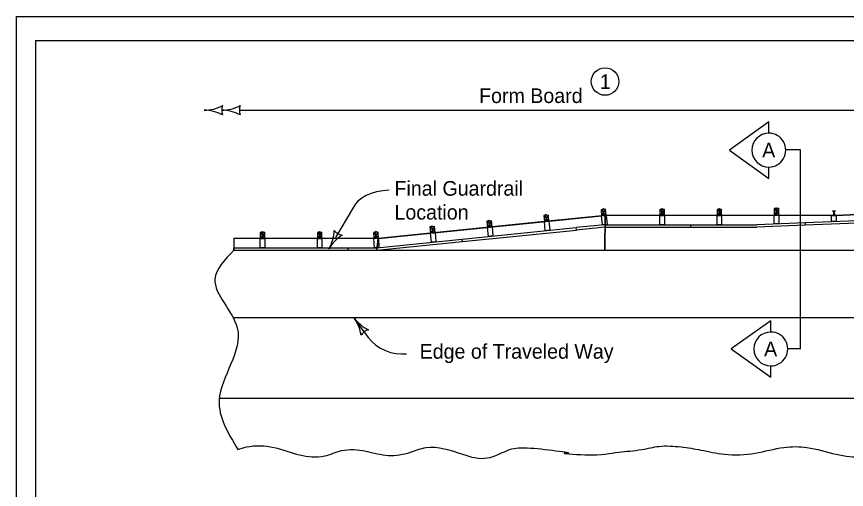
# Model space of a CAD drawing. Extents: x 6410 to 81668, y 3928 to 11667.
# Drawn here: x 10133 to 11038, y 9428 to 9944 of the extents above; entities that cross this region are included whole.
import ezdxf

# ---------------------------------------------------------------- set-up
doc = ezdxf.new("R2010")
doc.units = 0
for name, color, linetype in [('dsnCellElements', 7, 'Continuous'), ('dsnNonPlotable', 7, 'Continuous'), ('dsnShtPlotShapeBatchPrint', 7, 'Continuous'), ('dsnStdBlockModified', 7, 'Continuous'), ('Level 10', 7, 'Continuous'), ('Level 11', 7, 'Continuous'), ('Level 14', 7, 'Continuous'), ('Level 3', 7, 'Continuous'), ('Level 7', 7, 'Continuous'), ('Level 8', 7, 'Continuous')]:
    doc.layers.add(name, color=color, linetype=linetype)

msp = doc.modelspace()

# ---------------------------------------------------------------- linework, layer by layer
at = {"layer": 'dsnCellElements'}
for p, q in [((10499.16, 9734.25), (10480.61, 9702.91)), ((10512.77, 9599.09), (10500.66, 9615.54)), ((10552.86, 9576.02), (10558.31, 9576.02))]:
    msp.add_line(p, q, dxfattribs=at)
for centre, radius, start, end in [((10436.84, 9712.41), 42.5, 329.37973, 357.45222), ((10491.57, 9721.43), 16.42, 221.64638, 257.11308), ((10509.99, 9669.12), 42.5, 121.30724, 149.37973), ((10534.88, 9640.74), 42.5, 216.37256, 244.44505), ((10466.44, 9590.33), 42.5, 8.30007, 36.37256), ((10521.79, 9586.84), 16.42, 108.63921, 144.10591), ((10552.92, 9622.48), 46.46, 210.22743, 270)]:
    msp.add_arc(centre, radius, start, end, dxfattribs=at)
msp.add_ellipse((10580.25, 9695.21), major_axis=(-81.09, 39.04), ratio=0.555556, start_param=5.482641, end_param=6.283185, dxfattribs=at)
at = {"layer": 'dsnNonPlotable'}
for q in [(10153.18, 8307.9), (13248.87, 9917.9)]:
    msp.add_line((10153.18, 9917.9), q, dxfattribs=at)
at = {"layer": 'dsnShtPlotShapeBatchPrint'}
for p, q in [((10376.45, 9842.03), (11398.86, 9842.03)), ((11501.75, 9746.48), (11026.46, 9726.96)), ((10708.69, 9720.37), (10527.39, 9701.88)), ((10775.18, 9726.96), (10708.69, 9720.38)), ((10708.69, 9720.38), (10708.69, 9720.37)), ((10775.18, 9726.96), (10774.8, 9689.17)), ((10774.8, 9689.17), (10775.18, 9726.96)), ((11026.46, 9726.96), (10775.18, 9726.96)), ((10775.18, 9726.96), (10775.18, 9726.96)), ((10369.67, 9701.88), (10369.64, 9689.17)), ((10527.39, 9701.87), (10369.67, 9701.88)), ((10527.39, 9701.87), (10525.89, 9689.17)), ((10525.89, 9689.17), (10527.39, 9701.87)), ((10527.39, 9701.88), (10527.39, 9701.87)), ((10527.39, 9701.87), (10527.39, 9701.87)), ((10369.64, 9689.17), (10525.89, 9689.17)), ((10525.89, 9689.17), (10774.8, 9689.17)), ((10774.8, 9689.17), (11806.49, 9689.17))]:
    msp.add_line(p, q, dxfattribs=at)
for centre, radius, start, end in [((10337.23, 9884.37), 42.5, 270, 298.07249), ((10356.45, 9884.37), 42.5, 270, 298.07249), ((10372.87, 9841.87), 16.42, 162.26665, 197.73335), ((10392.09, 9841.87), 16.42, 162.26665, 197.73335), ((10337.23, 9799.37), 42.5, 61.92751, 90), ((10356.45, 9799.37), 42.5, 61.92751, 90)]:
    msp.add_arc(centre, radius, start, end, dxfattribs=at)
at = {"layer": 'dsnStdBlockModified'}
for p, q in [((11026.36, 9726.96), (11501.75, 9746.48)), ((11404.96, 9735.52), (10993.39, 9719.06)), ((11405.06, 9732.82), (10993.39, 9716.35)), ((11023.02, 9731.85), (11023.02, 9731.7)), ((11026.36, 9731.85), (11023.02, 9731.85)), ((11023.02, 9731.7), (11024.19, 9731.7)), ((11024.61, 9731.28), (11024.61, 9727.53)), ((11024.77, 9727.53), (11024.77, 9731.28)), ((11025.18, 9731.7), (11026.36, 9731.7)), ((11025.78, 9729.15), (11025.26, 9729.15)), ((11025.26, 9729.15), (11025.26, 9727.63)), ((11025.78, 9727.63), (11025.78, 9729.15)), ((11026.36, 9731.7), (11026.36, 9731.85)), ((10527.39, 9701.88), (10775.18, 9726.96)), ((11023.02, 9726.96), (10775.18, 9726.96)), ((11022.08, 9720.31), (11022.08, 9727.27)), ((11022.08, 9727.27), (11022.71, 9727.27)), ((11027.08, 9720.31), (11022.08, 9720.31)), ((11022.71, 9726.96), (11022.71, 9727.27)), ((11026.46, 9726.96), (11022.71, 9726.96)), ((11023.02, 9727.11), (11023.02, 9726.96)), ((11024.19, 9727.11), (11023.02, 9727.11)), ((11023.02, 9726.96), (11026.36, 9726.96)), ((11025, 9727.63), (11024.92, 9727.58)), ((11024.92, 9727.21), (11024.92, 9727.58)), ((11025, 9727.63), (11025.97, 9727.63)), ((11026.36, 9727.11), (11025.18, 9727.11)), ((11025.22, 9727.17), (11025.22, 9727.58)), ((11025.82, 9727.17), (11025.82, 9727.58)), ((11025.97, 9727.63), (11026.04, 9727.63)), ((11026.12, 9727.58), (11026.04, 9727.63)), ((11026.04, 9727.11), (11026.12, 9727.17)), ((11026.12, 9727.17), (11026.12, 9727.58)), ((11026.36, 9726.96), (11026.36, 9727.11)), ((11026.46, 9727.27), (11027.08, 9727.27)), ((11026.46, 9727.27), (11026.46, 9726.96)), ((11027.08, 9727.27), (11027.08, 9720.31)), ((10993.39, 9719.06), (10940.63, 9716.95)), ((10993.5, 9716.36), (10940.65, 9714.24)), ((10993.39, 9719.06), (10993.5, 9716.36)), ((10993.39, 9719.06), (10993.5, 9716.36)), ((10369.67, 9701.88), (10369.64, 9691.87)), ((10527.39, 9701.88), (10369.67, 9701.88)), ((10369.64, 9689.17), (11983.35, 9689.17)), ((10369.86, 9615.54), (11983.65, 9615.54))]:
    msp.add_line(p, q, dxfattribs=at)
for centre, start, end in [((11024.19, 9731.28), 359.99336, 90.00253), ((11025.18, 9731.28), 90.00734, 179.99635), ((11024.19, 9727.53), 270.00734, 359.99635), ((11025.18, 9727.53), 264.71743, 270.00253)]:
    msp.add_arc(centre, 0.417, start, end, dxfattribs=at)
for points in [[(11025.22, 9727.58), (11025.2, 9727.6), (11025.15, 9727.63), (11025.06, 9727.64), (11024.99, 9727.62), (11024.94, 9727.6), (11024.92, 9727.58)], [(11025.12, 9727.12), (11025.13, 9727.13), (11025.17, 9727.13), (11025.2, 9727.15), (11025.22, 9727.17)], [(11025.82, 9727.58), (11025.77, 9727.6), (11025.66, 9727.63), (11025.51, 9727.64), (11025.36, 9727.62), (11025.27, 9727.6), (11025.22, 9727.58)], [(11025.22, 9727.17), (11025.27, 9727.15), (11025.38, 9727.12), (11025.54, 9727.11), (11025.69, 9727.13), (11025.78, 9727.15), (11025.82, 9727.17)], [(11026.12, 9727.58), (11026.11, 9727.59), (11026.07, 9727.61), (11026.01, 9727.63), (11025.94, 9727.64), (11025.87, 9727.61), (11025.84, 9727.59), (11025.82, 9727.58)], [(11025.82, 9727.17), (11025.84, 9727.16), (11025.87, 9727.14), (11025.94, 9727.11), (11026.01, 9727.12), (11026.07, 9727.14), (11026.11, 9727.16), (11026.12, 9727.17)]]:
    msp.add_open_spline(points, degree=3, dxfattribs=at)
for points in [[(10369.64, 9689.17), (10348.99, 9657.61), (10373.36, 9604.53), (10353.66, 9525.43), (10373.93, 9471.82)], [(10373.93, 9471.82), (10383.36, 9474.4), (10413.58, 9473.83), (10441.52, 9465.84), (10468.89, 9464.7), (10487.14, 9470.4), (10513.94, 9469.83), (10538.46, 9465.27), (10562.41, 9468.69), (10579.52, 9473.83), (10619.43, 9466.41), (10646.23, 9462.42), (10670.75, 9471.54), (10693.56, 9473.26), (10732.34, 9467.55), (10731.77, 9467.55), (10752.92, 9465.95), (10789.99, 9468.8), (10815.08, 9471.65), (10833.9, 9475.08), (10857.85, 9474.5), (10879.51, 9471.08), (10905.17, 9466.52), (10938.82, 9467.66), (10970.18, 9473.93), (10995.27, 9473.93), (11027.2, 9466.52), (11056.29, 9463.67), (11089.93, 9470.51), (11122.43, 9473.93), (11156.65, 9467.09), (11182.31, 9464.24), (11204.54, 9467.66), (11232.49, 9483.06), (11242.75, 9485.34), (11267.27, 9487.63), (11297.93, 9488.2), (11319.03, 9488.2), (11372.34, 9478.91)]]:
    msp.add_spline(points, degree=3, dxfattribs=at)
at = {"layer": 'Level 10'}
for p, q in [((10988.26, 9798.63), (10972.49, 9798.63)), ((10988.26, 9581.35), (10988.26, 9798.63)), ((10988.26, 9581.35), (10974.31, 9581.35))]:
    msp.add_line(p, q, dxfattribs=at)
for points in [[(10953.7, 9816.82), (10953.7, 9829.14), (10910.57, 9798.33), (10953.7, 9767.52), (10953.7, 9779.84)], [(10955.82, 9599.83), (10955.82, 9612.16), (10912.69, 9581.35), (10955.82, 9550.54), (10955.82, 9562.86)]]:
    msp.add_lwpolyline(points, dxfattribs=at)
for centre, start, end in [((10953.7, 9798.33), 90.00083, 269.99917), ((10953.7, 9798.33), 269.99917, 90.00083), ((10955.82, 9581.35), 90.00083, 269.99917), ((10955.82, 9581.35), 269.99917, 90.00083)]:
    msp.add_arc(centre, 18.49, start, end, dxfattribs=at)
at = {"layer": 'Level 11'}
msp.add_line((10353.26, 9527.62), (11995.29, 9527.62), dxfattribs=at)
at = {"layer": 'Level 14'}
for p, q in [((10770.49, 9733.29), (10776.13, 9727.16)), ((10775.47, 9733.79), (10771.15, 9726.66)), ((10772.88, 9734.51), (10772.88, 9734.58)), ((10773.64, 9726.91), (10772.98, 9733.54)), ((10834.64, 9733.62), (10839.64, 9726.96)), ((10839.64, 9733.62), (10834.64, 9726.96)), ((10837.14, 9734.6), (10837.14, 9734.67)), ((10837.14, 9726.96), (10837.14, 9733.62)), ((10897.14, 9733.62), (10902.14, 9726.96)), ((10902.14, 9733.62), (10897.14, 9726.96)), ((10899.64, 9734.6), (10899.64, 9734.67)), ((10899.64, 9726.96), (10899.64, 9733.62)), ((10959.64, 9734.49), (10964.64, 9727.82)), ((10964.64, 9734.49), (10959.64, 9727.82)), ((10962.14, 9735.46), (10962.14, 9735.53)), ((10962.14, 9727.82), (10962.14, 9734.49)), ((10645.84, 9720.76), (10651.48, 9714.63)), ((10650.82, 9721.26), (10646.51, 9714.13)), ((10648.23, 9721.98), (10648.22, 9722.05)), ((10648.99, 9714.38), (10648.33, 9721.01)), ((10708.03, 9727.01), (10713.67, 9720.88)), ((10713, 9727.51), (10708.69, 9720.38)), ((10708.69, 9720.38), (10713.67, 9720.88)), ((10709.69, 9710.42), (10708.69, 9720.38)), ((10710.42, 9728.23), (10710.41, 9728.3)), ((10711.18, 9720.63), (10710.51, 9727.26)), ((10713.67, 9720.88), (10714.67, 9710.92)), ((10771.15, 9726.66), (10776.13, 9727.16)), ((10773.64, 9726.91), (10771.15, 9726.66)), ((10773.64, 9726.91), (10771.15, 9726.66)), ((10772.15, 9716.7), (10771.15, 9726.66)), ((10776.13, 9727.16), (10777.13, 9717.2)), ((10834.64, 9726.96), (10839.64, 9726.96)), ((10834.64, 9716.95), (10834.64, 9726.96)), ((10839.64, 9726.96), (10839.64, 9716.95)), ((10897.14, 9726.96), (10902.14, 9726.96)), ((10897.14, 9716.95), (10897.14, 9726.96)), ((10902.14, 9726.96), (10902.14, 9716.95)), ((10959.64, 9727.82), (10964.64, 9727.82)), ((10959.64, 9717.81), (10959.64, 9727.82)), ((10964.64, 9727.82), (10964.64, 9717.81)), ((10583.66, 9714.55), (10589.3, 9708.38)), ((10588.64, 9715.05), (10584.33, 9707.88)), ((10586.05, 9715.77), (10586.05, 9715.84)), ((10586.81, 9708.13), (10586.15, 9714.8)), ((10618.9, 9701.3), (10743.28, 9713.8)), ((10619.17, 9698.6), (10743.55, 9711.1)), ((10646.51, 9714.13), (10651.49, 9714.63)), ((10647.51, 9704.17), (10646.51, 9714.13)), ((10651.49, 9714.63), (10652.49, 9704.67)), ((10714.67, 9710.92), (10709.69, 9710.42)), ((10774.64, 9716.95), (10743.28, 9713.8)), ((10743.55, 9711.1), (10743.28, 9713.8)), ((10743.55, 9711.12), (10743.28, 9713.8)), ((10774.64, 9714.24), (10743.55, 9711.12)), ((10777.13, 9717.2), (10772.15, 9716.7)), ((10774.64, 9716.95), (10868.39, 9716.95)), ((10774.64, 9714.24), (10868.39, 9714.24)), ((10839.64, 9716.95), (10834.64, 9716.95)), ((10868.39, 9714.24), (10868.39, 9716.95)), ((10868.39, 9716.95), (10940.63, 9716.95)), ((10868.39, 9714.24), (10868.39, 9716.95)), ((10868.39, 9714.24), (10940.65, 9714.24)), ((10902.14, 9716.95), (10897.14, 9716.95)), ((10964.64, 9717.81), (10959.64, 9717.81)), ((10398.39, 9708.55), (10403.39, 9701.88)), ((10403.39, 9708.55), (10398.39, 9701.88)), ((10398.39, 9701.88), (10403.4, 9701.88)), ((10398.39, 9691.87), (10398.39, 9701.88)), ((10400.89, 9709.52), (10400.89, 9709.59)), ((10400.89, 9701.88), (10400.89, 9708.55)), ((10403.4, 9701.88), (10403.4, 9691.87)), ((10460.89, 9708.55), (10465.89, 9701.88)), ((10465.89, 9708.55), (10460.89, 9701.88)), ((10460.89, 9701.88), (10465.9, 9701.88)), ((10460.89, 9691.87), (10460.89, 9701.88)), ((10463.39, 9709.52), (10463.39, 9709.59)), ((10463.39, 9701.88), (10463.39, 9708.55)), ((10465.9, 9701.88), (10465.9, 9691.87)), ((10522.28, 9708.61), (10527.61, 9702.17)), ((10527.28, 9708.86), (10522.62, 9701.92)), ((10522.62, 9701.92), (10527.61, 9702.17)), ((10523.11, 9691.88), (10522.62, 9701.92)), ((10524.73, 9709.71), (10524.73, 9709.78)), ((10525.11, 9702.05), (10524.78, 9708.74)), ((10527.61, 9702.17), (10528.11, 9692.13)), ((10584.33, 9707.88), (10589.3, 9708.38)), ((10585.32, 9697.87), (10584.33, 9707.88)), ((10589.3, 9708.38), (10590.3, 9698.38)), ((10652.49, 9704.67), (10647.51, 9704.17)), ((10525.62, 9691.87), (10618.9, 9701.3)), ((10525.89, 9689.17), (10619.17, 9698.59)), ((10590.3, 9698.38), (10585.32, 9697.87)), ((10619.17, 9698.59), (10618.9, 9701.3)), ((10619.17, 9698.6), (10618.9, 9701.3)), ((10369.64, 9691.87), (10494.64, 9691.87)), ((10369.64, 9689.17), (10369.64, 9691.87)), ((10369.64, 9689.17), (10494.64, 9689.17)), ((10403.4, 9691.87), (10398.39, 9691.87)), ((10465.9, 9691.87), (10460.89, 9691.87)), ((10494.64, 9691.87), (10525.62, 9691.87)), ((10494.64, 9689.17), (10494.64, 9691.87)), ((10494.64, 9689.17), (10525.89, 9689.17)), ((10528.11, 9692.13), (10523.11, 9691.88))]:
    msp.add_line(p, q, dxfattribs=at)
for points in [[(10771.15, 9726.66), (10776.13, 9727.16), (10775.47, 9733.79), (10770.49, 9733.29)], [(10834.64, 9726.96), (10839.64, 9726.96), (10839.64, 9733.62), (10834.64, 9733.62)], [(10897.14, 9726.96), (10902.14, 9726.96), (10902.14, 9733.62), (10897.14, 9733.62)], [(10959.64, 9727.82), (10964.64, 9727.82), (10964.64, 9734.49), (10959.64, 9734.49)], [(10646.51, 9714.13), (10651.48, 9714.63), (10650.82, 9721.26), (10645.84, 9720.76)], [(10708.69, 9720.38), (10713.67, 9720.88), (10713, 9727.51), (10708.03, 9727.01)], [(10584.33, 9707.88), (10589.3, 9708.38), (10588.64, 9715.05), (10583.66, 9714.55)], [(10398.39, 9701.88), (10403.39, 9701.88), (10403.39, 9708.55), (10398.39, 9708.55)], [(10460.89, 9701.88), (10465.89, 9701.88), (10465.89, 9708.55), (10460.89, 9708.55)], [(10522.62, 9701.92), (10527.61, 9702.17), (10527.28, 9708.86), (10522.28, 9708.61)]]:
    msp.add_lwpolyline(points, close=True, dxfattribs=at)
for points in [[(10772.65, 9733.51), (10772.6, 9733.94), (10773.27, 9734), (10773.31, 9733.57)], [(10772.74, 9733.95), (10772.69, 9734.49), (10773.08, 9734.53), (10773.13, 9733.99)], [(10836.8, 9733.62), (10836.8, 9734.06), (10837.47, 9734.06), (10837.47, 9733.62)], [(10836.94, 9734.06), (10836.94, 9734.6), (10837.33, 9734.6), (10837.33, 9734.06)], [(10899.31, 9733.62), (10899.31, 9734.06), (10899.97, 9734.06), (10899.97, 9733.62)], [(10899.45, 9734.06), (10899.45, 9734.6), (10899.83, 9734.6), (10899.83, 9734.06)], [(10961.81, 9734.49), (10961.81, 9734.92), (10962.47, 9734.92), (10962.47, 9734.49)], [(10961.95, 9734.92), (10961.95, 9735.46), (10962.33, 9735.46), (10962.33, 9734.92)], [(10648, 9720.98), (10647.95, 9721.41), (10648.62, 9721.48), (10648.66, 9721.05)], [(10648.09, 9721.42), (10648.04, 9721.96), (10648.42, 9722), (10648.48, 9721.46)], [(10710.18, 9727.23), (10710.14, 9727.66), (10710.8, 9727.73), (10710.85, 9727.3)], [(10710.28, 9727.67), (10710.22, 9728.21), (10710.61, 9728.25), (10710.66, 9727.71)], [(10585.82, 9714.77), (10585.78, 9715.2), (10586.44, 9715.26), (10586.48, 9714.83)], [(10585.91, 9715.21), (10585.86, 9715.75), (10586.25, 9715.79), (10586.3, 9715.25)], [(10400.56, 9708.55), (10400.56, 9708.98), (10401.23, 9708.98), (10401.23, 9708.55)], [(10400.7, 9708.98), (10400.7, 9709.52), (10401.09, 9709.52), (10401.09, 9708.98)], [(10463.06, 9708.55), (10463.06, 9708.98), (10463.73, 9708.98), (10463.73, 9708.55)], [(10463.2, 9708.98), (10463.2, 9709.52), (10463.59, 9709.52), (10463.59, 9708.98)], [(10525.11, 9702.05), (10522.62, 9701.92), (10522.62, 9701.92)], [(10524.45, 9708.72), (10524.43, 9709.15), (10525.09, 9709.19), (10525.11, 9708.76)], [(10524.57, 9709.16), (10524.54, 9709.7), (10524.93, 9709.72), (10524.95, 9709.18)]]:
    msp.add_lwpolyline(points, dxfattribs=at)
at = {"layer": 'Level 3'}
for p, q in [((11026.36, 9731.85), (11023.02, 9731.85)), ((11023.02, 9731.85), (11023.02, 9731.7)), ((11023.02, 9731.85), (11023.02, 9731.7)), ((11026.36, 9731.85), (11023.02, 9731.85)), ((11023.02, 9731.7), (11024.19, 9731.7)), ((11023.02, 9731.7), (11024.19, 9731.7)), ((11024.61, 9731.28), (11024.61, 9727.53)), ((11024.61, 9731.28), (11024.61, 9727.53)), ((11024.77, 9727.53), (11024.77, 9731.28)), ((11024.77, 9727.53), (11024.77, 9731.28)), ((11025.18, 9731.7), (11026.36, 9731.7)), ((11025.18, 9731.7), (11026.36, 9731.7)), ((11025.78, 9729.15), (11025.26, 9729.15)), ((11025.26, 9729.15), (11025.26, 9727.63)), ((11025.78, 9729.15), (11025.26, 9729.15)), ((11025.26, 9729.15), (11025.26, 9727.63)), ((11025.78, 9727.63), (11025.78, 9729.15)), ((11025.78, 9727.63), (11025.78, 9729.15)), ((11026.36, 9731.7), (11026.36, 9731.85)), ((11026.36, 9731.7), (11026.36, 9731.85)), ((11022.08, 9720.31), (11022.08, 9727.27)), ((11022.08, 9727.27), (11022.71, 9727.27)), ((11027.08, 9720.31), (11022.08, 9720.31)), ((11022.71, 9726.96), (11022.71, 9727.27)), ((11026.46, 9726.96), (11022.71, 9726.96)), ((11024.19, 9727.11), (11023.02, 9727.11)), ((11023.02, 9727.11), (11023.02, 9726.96)), ((11023.02, 9727.11), (11023.02, 9726.96)), ((11024.19, 9727.11), (11023.02, 9727.11)), ((11023.02, 9726.96), (11026.36, 9726.96)), ((11023.02, 9726.96), (11026.36, 9726.96)), ((11025, 9727.63), (11024.92, 9727.58)), ((11025, 9727.63), (11024.92, 9727.58)), ((11024.92, 9727.58), (11024.92, 9727.21)), ((11024.92, 9727.21), (11024.92, 9727.58)), ((11025, 9727.63), (11025.97, 9727.63)), ((11025.97, 9727.63), (11025, 9727.63)), ((11026.36, 9727.11), (11025.18, 9727.11)), ((11026.36, 9727.11), (11025.18, 9727.11)), ((11025.22, 9727.58), (11025.22, 9727.17)), ((11025.22, 9727.17), (11025.22, 9727.58)), ((11025.22, 9727.17), (11025.22, 9727.58)), ((11025.26, 9727.63), (11025.78, 9727.63)), ((11025.82, 9727.17), (11025.82, 9727.58)), ((11025.82, 9727.58), (11025.82, 9727.17)), ((11025.82, 9727.17), (11025.82, 9727.58)), ((11025.97, 9727.63), (11026.04, 9727.63)), ((11026.04, 9727.63), (11025.97, 9727.63)), ((11026.12, 9727.58), (11026.04, 9727.63)), ((11026.12, 9727.58), (11026.04, 9727.63)), ((11026.04, 9727.11), (11026.12, 9727.17)), ((11026.04, 9727.11), (11026.12, 9727.17)), ((11026.12, 9727.17), (11026.12, 9727.58)), ((11026.12, 9727.17), (11026.12, 9727.58)), ((11026.36, 9726.96), (11026.36, 9727.11)), ((11026.36, 9726.96), (11026.36, 9727.11)), ((11026.46, 9727.27), (11027.08, 9727.27)), ((11026.46, 9727.27), (11026.46, 9726.96)), ((11027.08, 9727.27), (11027.08, 9720.31))]:
    msp.add_line(p, q, dxfattribs=at)
for points in [[(11024.92, 9727.21), (11024.92, 9727.21)], [(11025.18, 9727.11), (11026.04, 9727.11), (11026.04, 9727.11)]]:
    msp.add_lwpolyline(points, dxfattribs=at)
for centre, start, end in [((11024.19, 9731.28), 359.99336, 90.00253), ((11024.19, 9731.28), 359.99336, 90.00253), ((11025.18, 9731.28), 90.00734, 179.99635), ((11025.18, 9731.28), 90.00734, 179.99635), ((11024.19, 9727.53), 270.00734, 359.99635), ((11024.19, 9727.53), 270.00734, 359.99635), ((11025.18, 9727.53), 179.99336, 270.00253), ((11025.18, 9727.53), 179.99336, 270.00253), ((11025.18, 9727.53), 230.88662, 270.00253)]:
    msp.add_arc(centre, 0.417, start, end, dxfattribs=at)
for points in [[(11025.22, 9727.58), (11025.2, 9727.6), (11025.15, 9727.63), (11025.06, 9727.64), (11024.99, 9727.62), (11024.94, 9727.6), (11024.92, 9727.58)], [(11025.22, 9727.58), (11025.2, 9727.6), (11025.15, 9727.63), (11025.06, 9727.64), (11024.99, 9727.62), (11024.94, 9727.6), (11024.92, 9727.58)], [(11024.92, 9727.58), (11024.94, 9727.6), (11024.99, 9727.62), (11025.06, 9727.64), (11025.15, 9727.63), (11025.2, 9727.6), (11025.22, 9727.58)], [(11025.12, 9727.12), (11025.13, 9727.13), (11025.17, 9727.13), (11025.2, 9727.15), (11025.22, 9727.17)], [(11025.82, 9727.58), (11025.77, 9727.6), (11025.66, 9727.63), (11025.51, 9727.64), (11025.36, 9727.62), (11025.27, 9727.6), (11025.22, 9727.58)], [(11025.82, 9727.58), (11025.77, 9727.6), (11025.66, 9727.63), (11025.51, 9727.64), (11025.36, 9727.62), (11025.27, 9727.6), (11025.22, 9727.58)], [(11025.22, 9727.58), (11025.27, 9727.6), (11025.36, 9727.62), (11025.51, 9727.64), (11025.66, 9727.63), (11025.77, 9727.6), (11025.82, 9727.58)], [(11025.22, 9727.17), (11025.27, 9727.15), (11025.38, 9727.12), (11025.54, 9727.11), (11025.69, 9727.13), (11025.78, 9727.15), (11025.82, 9727.17)], [(11025.82, 9727.17), (11025.78, 9727.15), (11025.69, 9727.13), (11025.54, 9727.11), (11025.38, 9727.12), (11025.27, 9727.15), (11025.22, 9727.17)], [(11025.22, 9727.17), (11025.27, 9727.15), (11025.38, 9727.12), (11025.54, 9727.11), (11025.69, 9727.13), (11025.78, 9727.15), (11025.82, 9727.17)], [(11026.12, 9727.58), (11026.11, 9727.59), (11026.07, 9727.61), (11026.01, 9727.63), (11025.94, 9727.64), (11025.87, 9727.61), (11025.84, 9727.59), (11025.82, 9727.58)], [(11026.12, 9727.58), (11026.11, 9727.59), (11026.07, 9727.61), (11026.01, 9727.63), (11025.94, 9727.64), (11025.87, 9727.61), (11025.84, 9727.59), (11025.82, 9727.58)], [(11025.82, 9727.58), (11025.84, 9727.59), (11025.87, 9727.61), (11025.94, 9727.64), (11026.01, 9727.63), (11026.07, 9727.61), (11026.11, 9727.59), (11026.12, 9727.58)], [(11025.82, 9727.17), (11025.84, 9727.16), (11025.87, 9727.14), (11025.94, 9727.11), (11026.01, 9727.12), (11026.07, 9727.14), (11026.11, 9727.16), (11026.12, 9727.17)], [(11026.12, 9727.17), (11026.11, 9727.16), (11026.07, 9727.14), (11026.01, 9727.12), (11025.94, 9727.11), (11025.87, 9727.14), (11025.84, 9727.16), (11025.82, 9727.17)], [(11025.82, 9727.17), (11025.84, 9727.16), (11025.87, 9727.14), (11025.94, 9727.11), (11026.01, 9727.12), (11026.07, 9727.14), (11026.11, 9727.16), (11026.12, 9727.17)]]:
    msp.add_open_spline(points, degree=3, dxfattribs=at)
at = {"layer": 'Level 7'}
msp.add_circle((10774.85, 9873.16), 15, dxfattribs=at)
at = {"layer": 'Level 8'}
msp.add_lwpolyline([(10132.52, 9944.02), (13267.53, 9944.02), (13267.53, 7924.02), (10132.52, 7924.02)], close=True, dxfattribs=at)

# ---------------------------------------------------------------- texts
at = {"layer": 'dsnCellElements'}
for s, p in [('Final Guardrail ', (10545.06, 9748.58)), ('Location', (10545.06, 9722.58)), ('Edge of Traveled Way', (10572.5, 9570.74))]:
    msp.add_text(s, height=16, dxfattribs=at).set_placement(p)
at = {"layer": 'dsnShtPlotShapeBatchPrint'}
msp.add_text('Form Board', height=16, dxfattribs=at).set_placement((10637.4, 9849.72))
at = {"layer": 'Level 10'}
for p in [(10946.42, 9790.33), (10948.52, 9573.35)]:
    msp.add_text('A', height=16, dxfattribs=at).set_placement(p)
at = {"layer": 'Level 7'}
msp.add_text('1', height=16, dxfattribs=at).set_placement((10769.23, 9865.16))

doc.saveas('drawing.dxf')
